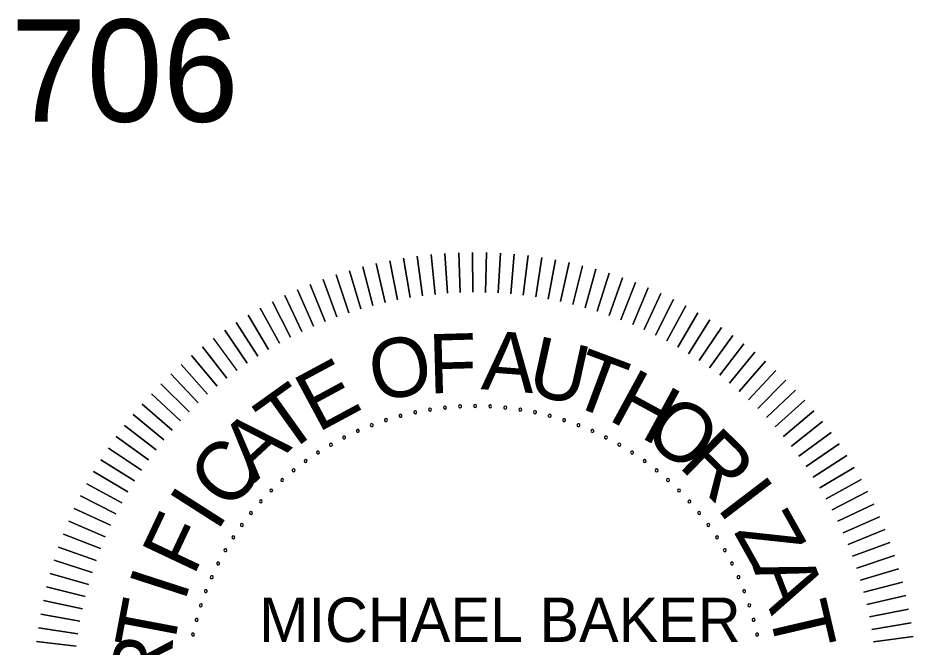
# Model space of a CAD drawing. Extents: x -712 to 3943, y 73 to 2823.
# Drawn here: x 2759.3 to 2969.5, y 316.9 to 464.5 of the extents above; entities that cross this region are included whole.
import ezdxf

# ---------------------------------------------------------------- set-up
doc = ezdxf.new("R2010")
doc.units = 0
doc.layers.add('Default', color=7, linetype='Continuous')
doc.layers.add('G-ANNO-TEXT', color=7, linetype='Continuous')

msp = doc.modelspace()

# ---------------------------------------------------------------- linework, layer by layer
at = {"layer": 'G-ANNO-TEXT'}
for points in [[(2851.37, 398.87), (2849.86, 408.1)], [(2849.86, 408.1), (2851.37, 398.87)], [(2854.3, 399.3), (2853.08, 408.57)], [(2853.08, 408.57), (2854.3, 399.3)], [(2857.25, 399.64), (2856.31, 408.95)], [(2856.31, 408.95), (2857.25, 399.64)], [(2860.2, 399.89), (2859.56, 409.22)], [(2859.56, 409.22), (2860.2, 399.89)], [(2863.16, 400.05), (2862.81, 409.4)], [(2862.81, 409.4), (2863.16, 400.05)], [(2866.12, 400.11), (2866.07, 409.46)], [(2866.07, 409.46), (2866.12, 400.11)], [(2869.09, 400.08), (2869.33, 409.43)], [(2869.33, 409.43), (2869.09, 400.08)], [(2872.05, 399.96), (2872.58, 409.3)], [(2872.58, 409.3), (2872.05, 399.96)], [(2875, 399.74), (2875.83, 409.06)], [(2875.83, 409.06), (2875, 399.74)], [(2877.95, 399.43), (2879.07, 408.72)], [(2879.07, 408.72), (2877.95, 399.43)], [(2880.89, 399.03), (2882.3, 408.28)], [(2882.3, 408.28), (2880.89, 399.03)], [(2883.81, 398.54), (2885.51, 407.74)], [(2885.51, 407.74), (2883.81, 398.54)], [(2842.68, 397.02), (2840.3, 406.06)], [(2840.3, 406.06), (2842.68, 397.02)], [(2845.55, 397.73), (2843.46, 406.84)], [(2843.46, 406.84), (2845.55, 397.73)], [(2848.45, 398.34), (2846.65, 407.52)], [(2846.65, 407.52), (2848.45, 398.34)], [(2886.72, 397.96), (2888.71, 407.09)], [(2888.71, 407.09), (2886.72, 397.96)], [(2889.6, 397.28), (2891.88, 406.35)], [(2891.88, 406.35), (2889.6, 397.28)], [(2836.99, 395.33), (2834.05, 404.21)], [(2834.05, 404.21), (2836.99, 395.33)], [(2839.82, 396.22), (2837.16, 405.19)], [(2837.16, 405.19), (2839.82, 396.22)], [(2892.47, 396.51), (2895.02, 405.51)], [(2895.02, 405.51), (2892.47, 396.51)], [(2895.3, 395.66), (2898.14, 404.57)], [(2898.14, 404.57), (2895.3, 395.66)], [(2898.11, 394.71), (2901.23, 403.53)], [(2901.23, 403.53), (2898.11, 394.71)], [(2831.43, 393.29), (2827.94, 401.97)], [(2827.94, 401.97), (2831.43, 393.29)], [(2834.19, 394.36), (2830.98, 403.14)], [(2830.98, 403.14), (2834.19, 394.36)], [(2900.89, 393.68), (2904.29, 402.4)], [(2904.29, 402.4), (2900.89, 393.68)], [(2826, 390.91), (2821.97, 399.35)], [(2821.97, 399.35), (2826, 390.91)], [(2828.7, 392.14), (2824.93, 400.71)], [(2824.93, 400.71), (2828.7, 392.14)], [(2903.64, 392.56), (2907.3, 401.17)], [(2907.3, 401.17), (2903.64, 392.56)], [(2906.34, 391.36), (2910.28, 399.84)], [(2910.28, 399.84), (2906.34, 391.36)], [(2823.35, 389.59), (2819.06, 397.9)], [(2819.06, 397.9), (2823.35, 389.59)], [(2909.01, 390.07), (2913.21, 398.42)], [(2913.21, 398.42), (2909.01, 390.07)], [(2820.74, 388.19), (2816.18, 396.36)], [(2816.18, 396.36), (2820.74, 388.19)], [(2911.64, 388.7), (2916.1, 396.92)], [(2916.1, 396.92), (2911.64, 388.7)], [(2914.22, 387.24), (2918.94, 395.32)], [(2918.94, 395.32), (2914.22, 387.24)], [(2815.65, 385.14), (2810.6, 393.01)], [(2810.6, 393.01), (2815.65, 385.14)], [(2818.17, 386.71), (2813.36, 394.73)], [(2813.36, 394.73), (2818.17, 386.71)], [(2916.76, 385.71), (2921.73, 393.63)], [(2921.73, 393.63), (2916.76, 385.71)], [(2813.18, 383.5), (2807.88, 391.21)], [(2807.88, 391.21), (2813.18, 383.5)], [(2919.24, 384.09), (2924.46, 391.86)], [(2924.46, 391.86), (2919.24, 384.09)], [(2810.77, 381.79), (2805.23, 389.32)], [(2921.68, 382.4), (2927.13, 390)], [(2927.13, 390), (2921.68, 382.4)], [(2808.41, 379.99), (2802.63, 387.35)], [(2802.63, 387.35), (2808.41, 379.99)], [(2924.06, 380.64), (2929.75, 388.06)], [(2929.75, 388.06), (2924.06, 380.64)], [(2806.1, 378.13), (2800.1, 385.3)], [(2800.1, 385.3), (2806.1, 378.13)], [(2926.38, 378.8), (2932.3, 386.04)], [(2932.3, 386.04), (2926.38, 378.8)], [(2803.86, 376.19), (2797.64, 383.17)], [(2797.64, 383.17), (2803.86, 376.19)], [(2928.65, 376.88), (2934.79, 383.93)], [(2934.79, 383.93), (2928.65, 376.88)], [(2801.68, 374.18), (2795.24, 380.96)], [(2795.24, 380.96), (2801.68, 374.18)], [(2937.21, 381.75), (2930.85, 374.9)], [(2930.85, 374.9), (2937.21, 381.75)], [(2799.56, 372.11), (2792.91, 378.68)], [(2792.91, 378.68), (2799.56, 372.11)], [(2939.57, 379.5), (2932.99, 372.85)], [(2932.99, 372.85), (2939.57, 379.5)], [(2797.51, 369.97), (2790.66, 376.33)], [(2790.66, 376.33), (2797.51, 369.97)], [(2941.85, 377.17), (2935.06, 370.73)], [(2935.06, 370.73), (2941.85, 377.17)], [(2944.05, 374.78), (2937.07, 368.55)], [(2937.07, 368.55), (2944.05, 374.78)], [(2795.53, 367.76), (2788.48, 373.91)], [(2788.48, 373.91), (2795.53, 367.76)], [(2946.18, 372.31), (2939.01, 366.31)], [(2939.01, 366.31), (2946.18, 372.31)], [(2793.62, 365.5), (2786.38, 371.42)], [(2786.38, 371.42), (2793.62, 365.5)], [(2791.78, 363.18), (2784.36, 368.87)], [(2784.36, 368.87), (2791.78, 363.18)], [(2948.23, 369.78), (2940.88, 364.01)], [(2940.88, 364.01), (2948.23, 369.78)], [(2790.01, 360.8), (2782.41, 366.25)], [(2782.41, 366.25), (2790.01, 360.8)], [(2950.2, 367.19), (2942.67, 361.65)], [(2942.67, 361.65), (2950.2, 367.19)], [(2788.32, 358.36), (2780.56, 363.58)], [(2780.56, 363.58), (2788.32, 358.36)], [(2952.09, 364.53), (2944.39, 359.23)], [(2944.39, 359.23), (2952.09, 364.53)], [(2953.9, 361.82), (2946.03, 356.76)], [(2946.03, 356.76), (2953.9, 361.82)], [(2786.71, 355.88), (2778.78, 360.84)], [(2778.78, 360.84), (2786.71, 355.88)], [(2785.17, 353.34), (2777.1, 358.06)], [(2777.1, 358.06), (2785.17, 353.34)], [(2955.61, 359.05), (2947.59, 354.24)], [(2947.59, 354.24), (2955.61, 359.05)], [(2783.72, 350.76), (2775.5, 355.22)], [(2775.5, 355.22), (2783.72, 350.76)], [(2957.24, 356.23), (2949.07, 351.68)], [(2949.07, 351.68), (2957.24, 356.23)], [(2958.78, 353.36), (2950.47, 349.07)], [(2950.47, 349.07), (2958.78, 353.36)], [(2782.35, 348.13), (2773.99, 352.33)], [(2773.99, 352.33), (2782.35, 348.13)], [(2781.06, 345.46), (2772.57, 349.4)], [(2772.57, 349.4), (2781.06, 345.46)], [(2960.23, 350.44), (2951.79, 346.41)], [(2951.79, 346.41), (2960.23, 350.44)], [(2961.59, 347.48), (2953.03, 343.72)], [(2953.03, 343.72), (2961.59, 347.48)], [(2779.85, 342.75), (2771.25, 346.42)], [(2771.25, 346.42), (2779.85, 342.75)], [(2778.73, 340.01), (2770.02, 343.4)], [(2770.02, 343.4), (2778.73, 340.01)], [(2962.85, 344.48), (2954.18, 340.99)], [(2954.18, 340.99), (2962.85, 344.48)], [(2964.02, 341.44), (2955.24, 338.22)], [(2955.24, 338.22), (2964.02, 341.44)], [(2777.7, 337.23), (2768.88, 340.35)], [(2768.88, 340.35), (2777.7, 337.23)], [(2965.09, 338.36), (2956.22, 335.42)], [(2956.22, 335.42), (2965.09, 338.36)], [(2776.76, 334.42), (2767.85, 337.26)], [(2767.85, 337.26), (2776.76, 334.42)], [(2775.9, 331.58), (2766.91, 334.14)], [(2766.91, 334.14), (2775.9, 331.58)], [(2966.07, 335.25), (2957.1, 332.59)], [(2957.1, 332.59), (2966.07, 335.25)], [(2966.95, 332.11), (2957.9, 329.74)], [(2957.9, 329.74), (2966.95, 332.11)], [(2775.13, 328.72), (2766.06, 330.99)], [(2766.06, 330.99), (2775.13, 328.72)], [(2774.46, 325.83), (2765.32, 327.82)], [(2765.32, 327.82), (2774.46, 325.83)], [(2967.72, 328.95), (2958.61, 326.86)], [(2958.61, 326.86), (2967.72, 328.95)], [(2968.4, 325.76), (2959.23, 323.96)], [(2959.23, 323.96), (2968.4, 325.76)], [(2773.87, 322.93), (2764.68, 324.63)], [(2764.68, 324.63), (2773.87, 322.93)], [(2968.98, 322.56), (2959.75, 321.04)], [(2959.75, 321.04), (2968.98, 322.56)], [(2773.38, 320.01), (2764.14, 321.42)], [(2764.14, 321.42), (2773.38, 320.01)], [(2772.98, 317.07), (2763.69, 318.19)], [(2763.69, 318.19), (2772.98, 317.07)], [(2969.46, 319.34), (2960.19, 318.11)], [(2960.19, 318.11), (2969.46, 319.34)]]:
    msp.add_lwpolyline(points, dxfattribs=at)
for centre, start, end in [((2852.58, 371.97), 12, 192), ((2852.58, 371.97), 192, 12), ((2856.06, 372.61), 9, 189), ((2856.06, 372.61), 189, 9), ((2859.57, 373.07), 6, 186), ((2859.57, 373.07), 186, 6), ((2863.11, 373.35), 3, 183), ((2863.11, 373.35), 183, 3), ((2866.65, 373.44), 0, 180), ((2866.65, 373.44), 180, 0), ((2870.19, 373.35), 357, 177), ((2870.19, 373.35), 177, 357), ((2873.72, 373.07), 354, 174), ((2873.72, 373.07), 174, 354), ((2877.24, 372.61), 351, 171), ((2877.24, 372.61), 171, 351), ((2880.72, 371.97), 168, 348), ((2880.72, 371.97), 348, 168), ((2845.73, 370.13), 18, 198), ((2845.73, 370.13), 198, 18), ((2849.13, 371.14), 15, 195), ((2849.13, 371.14), 195, 15), ((2884.17, 371.14), 165, 345), ((2884.17, 371.14), 345, 165), ((2887.56, 370.13), 162, 342), ((2887.56, 370.13), 342, 162), ((2839.12, 367.59), 24, 204), ((2839.12, 367.59), 204, 24), ((2842.39, 368.95), 21, 201), ((2842.39, 368.95), 201, 21), ((2890.9, 368.95), 159, 339), ((2890.9, 368.95), 339, 159), ((2894.18, 367.59), 156, 336), ((2894.18, 367.59), 336, 156), ((2835.92, 366.07), 27, 207), ((2835.92, 366.07), 207, 27), ((2897.37, 366.07), 153, 333), ((2897.37, 366.07), 333, 153), ((2832.81, 364.38), 30, 210), ((2832.81, 364.38), 210, 30), ((2900.49, 364.38), 150, 330), ((2900.49, 364.38), 330, 150), ((2829.79, 362.53), 33, 213), ((2829.79, 362.53), 213, 33), ((2903.51, 362.53), 147, 327), ((2903.51, 362.53), 327, 147), ((2826.87, 360.52), 36, 216), ((2826.87, 360.52), 216, 36), ((2906.43, 360.52), 144, 324), ((2906.43, 360.52), 324, 144), ((2824.06, 358.36), 39, 219), ((2824.06, 358.36), 219, 39), ((2909.24, 358.36), 141, 321), ((2909.24, 358.36), 321, 141), ((2821.36, 356.06), 42, 222), ((2821.36, 356.06), 222, 42), ((2911.93, 356.06), 138, 318), ((2911.93, 356.06), 318, 138), ((2818.79, 353.62), 45, 225), ((2818.79, 353.62), 225, 45), ((2914.5, 353.62), 135, 315), ((2914.5, 353.62), 315, 135), ((2816.35, 351.05), 48, 228), ((2816.35, 351.05), 228, 48), ((2916.94, 351.05), 132, 312), ((2916.94, 351.05), 312, 132), ((2814.05, 348.36), 51, 231), ((2814.05, 348.36), 231, 51), ((2919.24, 348.36), 129, 309), ((2919.24, 348.36), 309, 129), ((2811.9, 345.55), 54, 234), ((2811.9, 345.55), 234, 54), ((2921.4, 345.55), 126, 306), ((2921.4, 345.55), 306, 126), ((2809.89, 342.63), 57, 237), ((2809.89, 342.63), 237, 57), ((2923.41, 342.63), 123, 303), ((2923.41, 342.63), 303, 123), ((2808.04, 339.61), 60, 240), ((2808.04, 339.61), 240, 60), ((2925.26, 339.61), 120, 300), ((2925.26, 339.61), 300, 120), ((2806.35, 336.49), 63, 243), ((2806.35, 336.49), 243, 63), ((2926.95, 336.49), 117, 297), ((2926.95, 336.49), 297, 117), ((2804.82, 333.29), 66, 246), ((2804.82, 333.29), 246, 66), ((2928.48, 333.29), 114, 294), ((2928.48, 333.29), 294, 114), ((2803.46, 330.02), 69, 249), ((2803.46, 330.02), 249, 69), ((2929.83, 330.02), 111, 291), ((2929.83, 330.02), 291, 111), ((2802.28, 326.68), 72, 252), ((2802.28, 326.68), 252, 72), ((2931.02, 326.68), 108, 288), ((2931.02, 326.68), 288, 108), ((2801.28, 323.28), 75, 255), ((2801.28, 323.28), 255, 75), ((2932.02, 323.28), 105, 285), ((2932.02, 323.28), 285, 105), ((2800.45, 319.84), 78, 258), ((2800.45, 319.84), 258, 78), ((2932.85, 319.84), 102, 282), ((2932.85, 319.84), 282, 102)]:
    msp.add_arc(centre, 0.347, start, end, dxfattribs=at)

# ---------------------------------------------------------------- texts
at = {"layer": 'Default'}
msp.add_text('LOG MILE 1.706', height=24, dxfattribs=at).set_placement((2570.34, 440.13))
at = {"layer": 'G-ANNO-TEXT'}
for s, rotation, p in [('A', 355.5955, (2867.91, 377.4)), ('O', 10.7295, (2843.18, 374.37)), ('F', 1.5867, (2855.87, 376.38)), ('U', 347.5481, (2878.42, 376.4)), ('T', 339.5007, (2888.12, 374.09)), ('E', 28.279, (2829.7, 367.09)), ('H', 331.4533, (2897.54, 370.37)), ('T', 35.5725, (2821.94, 361.72)), ('O', 323.4059, (2905.51, 365.98)), ('A', 42.8659, (2814.89, 355.3)), ('R', 315.3585, (2914.12, 359.4)), ('C', 50.1594, (2809.04, 348.36)), ('I', 307.3112, (2923.15, 349.61)), ('I', 57.4529, (2806.03, 343.71)), ('F', 64.7464, (2800.58, 333.33)), ('Z', 299.2638, (2927.23, 343.95)), ('I', 72.0398, (2798.42, 327.22)), ('A', 291.2164, (2931.78, 335.6)), ('T', 79.3333, (2795.66, 315.25)), ('T', 283.169, (2935.41, 325.77)), ('R', 86.6268, (2795.03, 306.07))]:
    msp.add_text(s, height=13.89, rotation=rotation, dxfattribs=at).set_placement(p)
msp.add_text('MICHAEL BAKER', height=10.418, dxfattribs=at).set_placement((2815.96, 318.08))

doc.saveas('drawing.dxf')
